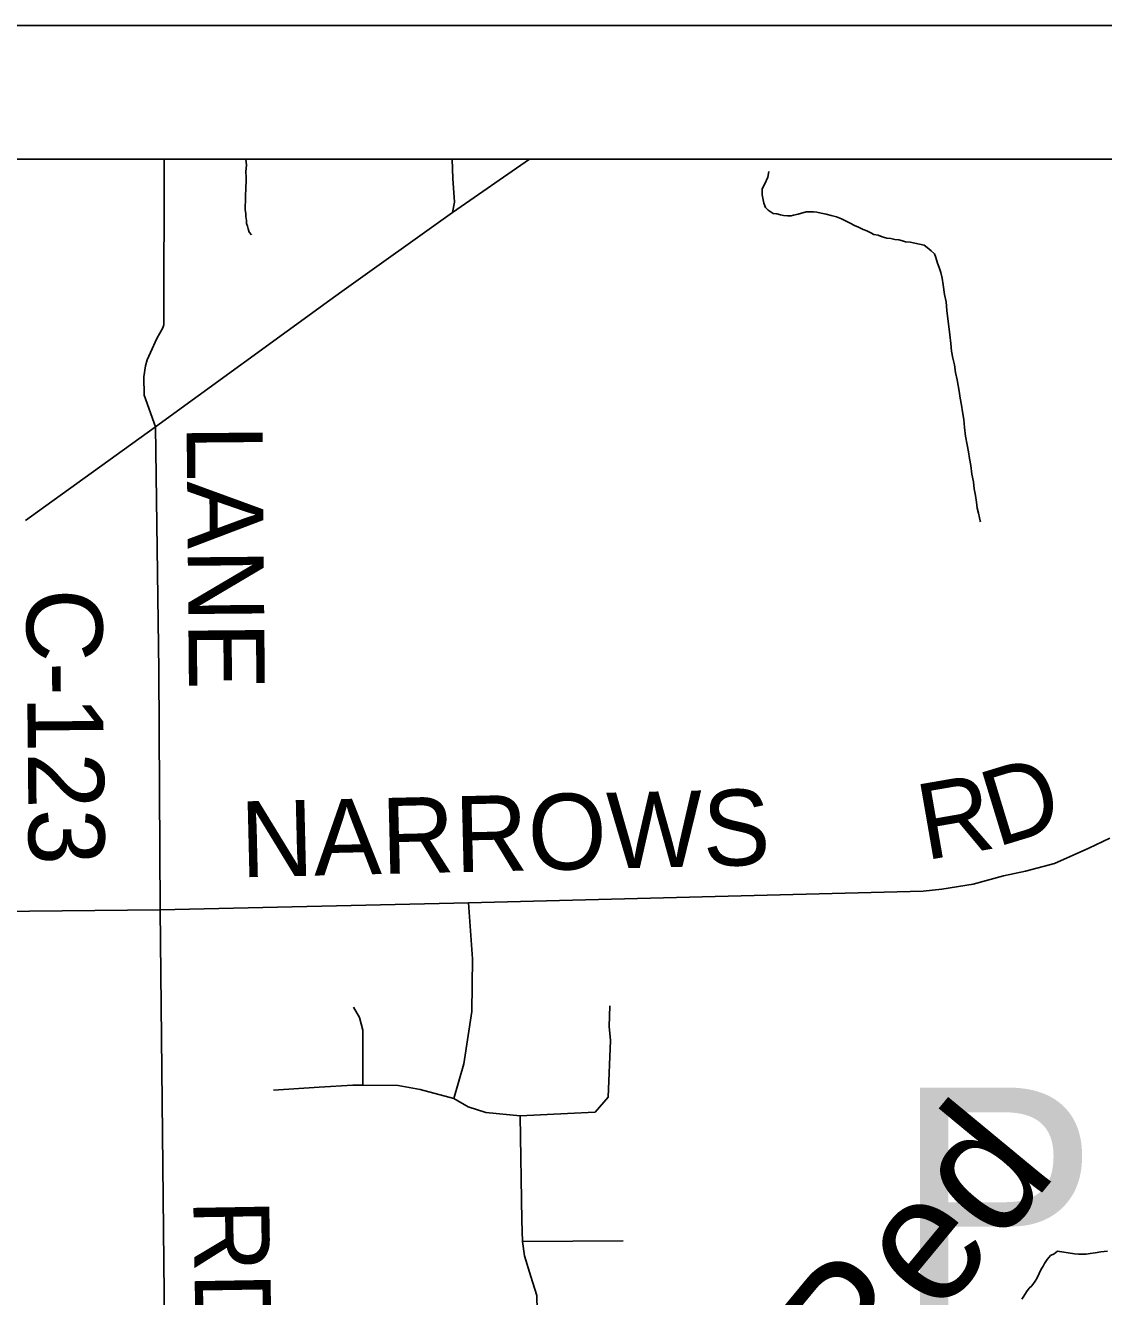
# Model space of a CAD drawing. Extents: x -59 to 82, y -3 to 49.
# Drawn here: x -50.187 to -49.38, y 48.44 to 49.391 of the extents above; entities that cross this region are included whole.
import ezdxf

# ---------------------------------------------------------------- set-up
doc = ezdxf.new("R2010")
doc.units = 0
for name, color, linetype in [('GM_X_Corporation', 7, 'Continuous'), ('GM_X_County_Road', 7, 'Continuous'), ('GM_X_County_Road_Text', 7, 'Continuous'), ('GM_X_Minor_River', 7, 'Continuous'), ('GM_X_Minor_River_Text', 7, 'Continuous'), ('GM_X_Township_Road', 7, 'Continuous'), ('GM_X_Township_Text', 7, 'Continuous'), ('GM_X_US_Route', 7, 'Continuous'), ('SH_Data', 7, 'Continuous')]:
    doc.layers.add(name, color=color, linetype=linetype)

msp = doc.modelspace()

# ---------------------------------------------------------------- linework, layer by layer
at = {"layer": 'GM_X_Corporation'}
for q in [(-52.22423, 49.29125), (-50.61637, 49.29125)]:
    msp.add_line((-48.09799, 49.29125), q, dxfattribs=at)
at = {"layer": 'GM_X_County_Road'}
for p, q in [((-49.86685, 49.27668), (-49.86733, 49.29125)), ((-49.86551, 49.25902), (-49.86685, 49.27668)), ((-49.86708, 49.2512), (-49.86551, 49.25902)), ((-50.08932, 49.09087), (-50.0869, 48.90877)), ((-50.0869, 48.90877), (-50.08577, 48.72919)), ((-49.39063, 48.77544), (-49.37487, 48.78285)), ((-49.41646, 48.76386), (-49.39063, 48.77544)), ((-49.43812, 48.75822), (-49.41646, 48.76386)), ((-49.4773, 48.74842), (-49.45445, 48.75466)), ((-49.45445, 48.75466), (-49.43812, 48.75822)), ((-49.85497, 48.7345), (-49.5147, 48.74338)), ((-49.5147, 48.74338), (-49.50075, 48.74486)), ((-49.50075, 48.74486), (-49.4773, 48.74842)), ((-50.08577, 48.72919), (-49.85497, 48.7345)), ((-50.26352, 48.72766), (-50.08577, 48.72919)), ((-50.08577, 48.72919), (-50.08012, 48.18116))]:
    msp.add_line(p, q, dxfattribs=at)
at = {"layer": 'GM_X_Minor_River'}
for p, q in [((-50.02174, 49.29125), (-50.02128, 49.2866)), ((-50.02128, 49.2866), (-50.02157, 49.28203)), ((-50.02157, 49.28203), (-50.02148, 49.27747)), ((-50.02148, 49.27747), (-50.02141, 49.27405)), ((-49.6309, 49.27773), (-49.63308, 49.27274)), ((-49.63022, 49.28193), (-49.6309, 49.27773)), ((-49.6309, 49.27773), (-49.63022, 49.28193)), ((-49.63022, 49.28193), (-49.6309, 49.27773)), ((-50.02166, 49.26796), (-50.02198, 49.26492)), ((-50.02198, 49.26492), (-50.02193, 49.26225)), ((-50.02141, 49.27405), (-50.02172, 49.27062)), ((-50.02172, 49.27062), (-50.02166, 49.26796)), ((-49.63308, 49.27274), (-49.63529, 49.2689)), ((-49.63529, 49.2689), (-49.6352, 49.26434)), ((-50.02188, 49.25959), (-50.02219, 49.25617)), ((-50.02219, 49.25617), (-50.02212, 49.25312)), ((-50.02193, 49.26225), (-50.02188, 49.25959)), ((-49.6352, 49.26434), (-49.63393, 49.25828)), ((-49.63393, 49.25828), (-49.63272, 49.25488)), ((-50.02212, 49.25312), (-50.02169, 49.25047)), ((-50.02169, 49.25047), (-50.02164, 49.24819)), ((-50.02164, 49.24819), (-50.0212, 49.24516)), ((-49.63272, 49.25488), (-49.63077, 49.25302)), ((-49.63077, 49.25302), (-49.62691, 49.25044)), ((-49.62691, 49.25044), (-49.62424, 49.25011)), ((-49.62424, 49.25011), (-49.62155, 49.2494)), ((-49.62155, 49.2494), (-49.61926, 49.24907)), ((-49.61926, 49.24907), (-49.61621, 49.24875)), ((-49.61621, 49.24875), (-49.61354, 49.24881)), ((-49.61354, 49.24881), (-49.61164, 49.24922)), ((-49.61164, 49.24922), (-49.60823, 49.25005)), ((-49.60823, 49.25005), (-49.60217, 49.2517)), ((-49.60217, 49.2517), (-49.60026, 49.25174)), ((-49.60026, 49.25174), (-49.59684, 49.25181)), ((-49.59684, 49.25181), (-49.59416, 49.25148)), ((-49.59416, 49.25148), (-49.5911, 49.25078)), ((-49.5911, 49.25078), (-49.58727, 49.2501)), ((-49.58727, 49.2501), (-49.58344, 49.24903)), ((-49.58344, 49.24903), (-49.57961, 49.24797)), ((-49.57961, 49.24797), (-49.57577, 49.24653)), ((-49.57577, 49.24653), (-49.5723, 49.2447)), ((-50.0212, 49.24516), (-50.02115, 49.24288)), ((-50.02115, 49.24288), (-50.02035, 49.24099)), ((-50.02035, 49.24099), (-50.01993, 49.2391)), ((-50.01993, 49.2391), (-50.01912, 49.23645)), ((-50.01912, 49.23645), (-50.01755, 49.23459)), ((-49.5723, 49.2447), (-49.56922, 49.24324)), ((-49.56922, 49.24324), (-49.56614, 49.2414)), ((-49.56614, 49.2414), (-49.56307, 49.24032)), ((-49.56307, 49.24032), (-49.5596, 49.23849)), ((-49.5596, 49.23849), (-49.55691, 49.23741)), ((-49.55691, 49.23741), (-49.55383, 49.23595)), ((-49.55383, 49.23595), (-49.55152, 49.23485)), ((-49.55152, 49.23485), (-49.54846, 49.23416)), ((-49.54846, 49.23416), (-49.54539, 49.23308)), ((-49.54539, 49.23308), (-49.54194, 49.23201)), ((-49.54194, 49.23201), (-49.53889, 49.23169)), ((-49.53889, 49.23169), (-49.53582, 49.23099)), ((-49.53582, 49.23099), (-49.53277, 49.23067)), ((-49.53277, 49.23067), (-49.53009, 49.22996)), ((-49.53009, 49.22996), (-49.52779, 49.22925)), ((-49.52779, 49.22925), (-49.52435, 49.22894)), ((-49.52435, 49.22894), (-49.5209, 49.22825)), ((-49.5209, 49.22825), (-49.51746, 49.22756)), ((-49.51746, 49.22756), (-49.51402, 49.22687)), ((-49.51402, 49.22687), (-49.51169, 49.22502)), ((-49.51169, 49.22502), (-49.50859, 49.22242)), ((-49.50859, 49.22242), (-49.50626, 49.22018)), ((-49.50626, 49.22018), (-49.50506, 49.21755)), ((-49.50506, 49.21755), (-49.50383, 49.21339)), ((-49.50383, 49.21339), (-49.50262, 49.20999)), ((-49.50262, 49.20999), (-49.5014, 49.20621)), ((-49.5014, 49.20621), (-49.50056, 49.20205)), ((-49.50056, 49.20205), (-49.49969, 49.19712)), ((-49.49969, 49.19712), (-49.49878, 49.18992)), ((-49.49878, 49.18992), (-49.49753, 49.18424)), ((-49.49753, 49.18424), (-49.49701, 49.17779)), ((-49.49701, 49.17779), (-49.49474, 49.15958)), ((-49.49474, 49.15958), (-49.49384, 49.15314)), ((-49.49384, 49.15314), (-49.49334, 49.14744)), ((-49.49334, 49.14744), (-49.49247, 49.14214)), ((-49.49247, 49.14214), (-49.49123, 49.13722)), ((-49.49123, 49.13722), (-49.49035, 49.13154)), ((-49.49035, 49.13154), (-49.48909, 49.12586)), ((-49.48909, 49.12586), (-49.48778, 49.11752)), ((-49.48778, 49.11752), (-49.48691, 49.11221)), ((-49.48691, 49.11221), (-49.48604, 49.10691)), ((-49.48604, 49.10691), (-49.48518, 49.10198)), ((-49.48518, 49.10198), (-49.4843, 49.0963)), ((-49.4843, 49.0963), (-49.48379, 49.09022)), ((-49.48379, 49.09022), (-49.4829, 49.08378)), ((-49.4829, 49.08378), (-49.48162, 49.07734)), ((-49.48162, 49.07734), (-49.48076, 49.07204)), ((-49.48076, 49.07204), (-49.47989, 49.06711)), ((-49.47989, 49.06711), (-49.47902, 49.06181)), ((-49.47902, 49.06181), (-49.47813, 49.05536)), ((-49.47813, 49.05536), (-49.47687, 49.04968)), ((-49.47687, 49.04968), (-49.47638, 49.04437)), ((-49.47638, 49.04437), (-49.47552, 49.03945)), ((-49.47552, 49.03945), (-49.47465, 49.03452)), ((-49.47465, 49.03452), (-49.47418, 49.02997)), ((-49.47418, 49.02997), (-49.47334, 49.02618)), ((-49.47334, 49.02618), (-49.47251, 49.02277)), ((-49.47251, 49.02277), (-49.47208, 49.0205)), ((-49.47208, 49.0205), (-49.47168, 49.01975)), ((-49.42377, 48.46448), (-49.42193, 48.46756)), ((-49.42193, 48.46756), (-49.41932, 48.47065)), ((-49.41932, 48.47065), (-49.41668, 48.47185)), ((-49.41668, 48.47185), (-49.41405, 48.47381)), ((-49.41405, 48.47381), (-49.40143, 48.47178)), ((-49.40143, 48.47178), (-49.39838, 48.47146)), ((-49.39838, 48.47146), (-49.39495, 48.47153)), ((-49.39495, 48.47153), (-49.39267, 48.47158)), ((-49.39267, 48.47158), (-49.38963, 48.47202)), ((-49.38963, 48.47202), (-49.38583, 48.47248)), ((-49.38583, 48.47248), (-49.38165, 48.47332)), ((-49.38165, 48.47332), (-49.37671, 48.4738)), ((-49.42964, 48.45334), (-49.42781, 48.45717)), ((-49.42781, 48.45717), (-49.42635, 48.46024)), ((-49.42635, 48.46024), (-49.42487, 48.46256)), ((-49.42487, 48.46256), (-49.42377, 48.46448)), ((-49.4352, 48.446), (-49.43334, 48.44794)), ((-49.43334, 48.44794), (-49.43074, 48.45141)), ((-49.43074, 48.45141), (-49.42964, 48.45334)), ((-49.44076, 48.4379), (-49.43928, 48.44021)), ((-49.43928, 48.44021), (-49.43743, 48.44329)), ((-49.43743, 48.44329), (-49.4352, 48.446))]:
    msp.add_line(p, q, dxfattribs=at)
at = {"layer": 'GM_X_Township_Road'}
for p, q in [((-50.08317, 49.16714), (-50.08279, 49.29125)), ((-50.08836, 49.15702), (-50.08382, 49.16502)), ((-50.08382, 49.16502), (-50.08317, 49.16714)), ((-50.09311, 49.1465), (-50.08836, 49.15702)), ((-50.09679, 49.13658), (-50.0956, 49.14094)), ((-50.0956, 49.14094), (-50.09311, 49.1465)), ((-50.09798, 49.12829), (-50.09679, 49.13658)), ((-50.09772, 49.11458), (-50.09798, 49.12829)), ((-50.08932, 49.09087), (-50.09772, 49.11458)), ((-49.85194, 48.69267), (-49.85497, 48.7345)), ((-49.8525, 48.65331), (-49.85194, 48.69267)), ((-49.93668, 48.64863), (-49.94108, 48.65634)), ((-49.7496, 48.64203), (-49.74933, 48.65744)), ((-49.93421, 48.63928), (-49.93668, 48.64863)), ((-49.85847, 48.61402), (-49.8525, 48.65331)), ((-49.93416, 48.59798), (-49.93421, 48.63928)), ((-49.74878, 48.63157), (-49.7496, 48.64203)), ((-49.75042, 48.58907), (-49.74878, 48.63157)), ((-49.86589, 48.58818), (-49.85847, 48.61402)), ((-50.00106, 48.59442), (-49.96682, 48.59649)), ((-49.96682, 48.59649), (-49.94159, 48.59798)), ((-49.94159, 48.59798), (-49.93416, 48.59798)), ((-49.93416, 48.59798), (-49.90775, 48.59769)), ((-49.90775, 48.59769), (-49.89112, 48.59472)), ((-49.89112, 48.59472), (-49.86589, 48.58818)), ((-49.86589, 48.58818), (-49.85521, 48.58195)), ((-49.85521, 48.58195), (-49.84215, 48.57749)), ((-49.76021, 48.57779), (-49.75042, 48.58907)), ((-49.84215, 48.57749), (-49.81632, 48.57512)), ((-49.81632, 48.57512), (-49.781, 48.5769)), ((-49.81513, 48.49673), (-49.81632, 48.57512)), ((-49.781, 48.5769), (-49.76021, 48.57779)), ((-49.81454, 48.48099), (-49.81513, 48.49673)), ((-49.81454, 48.48099), (-49.73914, 48.48158)), ((-49.81305, 48.4703), (-49.81454, 48.48099)), ((-49.80843, 48.45473), (-49.81305, 48.4703)), ((-49.80373, 48.44064), (-49.80843, 48.45473)), ((-49.80256, 48.3863), (-49.80373, 48.44064))]:
    msp.add_line(p, q, dxfattribs=at)
at = {"layer": 'GM_X_US_Route'}
for p, q in [((-49.86708, 49.2512), (-49.80941, 49.29125)), ((-49.94982, 49.19217), (-49.86708, 49.2512)), ((-49.95892, 49.18568), (-49.94982, 49.19217)), ((-50.08932, 49.09087), (-49.95892, 49.18568)), ((-50.17767, 49.02719), (-50.08932, 49.09087)), ((-50.18669, 49.02081), (-50.17767, 49.02719))]:
    msp.add_line(p, q, dxfattribs=at)
at = {"layer": 'SH_Data'}
for p, q in [((-54.99799, 49.39125), (-47.99799, 49.39125)), ((-54.89799, 49.29125), (-48.09799, 49.29125))]:
    msp.add_line(p, q, dxfattribs=at)

# ---------------------------------------------------------------- texts
at = {"layer": 'GM_X_County_Road_Text'}
for s, height, rotation, p in [('LANE', 0.056818, 270.51589, (-50.06603, 49.09226)), ('C-123', 0.056818, 270.55166, (-50.18606, 48.96945)), ('D', 0.05682, 16.96814, (-49.45976, 48.77603)), ('R', 0.05682, 9.84859, (-49.51311, 48.76629)), ('NARROWS', 0.056818, 1.37094, (-50.02522, 48.75358)), ('RD', 0.056818, 270.98725, (-50.06104, 48.51244))]:
    msp.add_text(s, height=height, rotation=rotation, dxfattribs=at).set_placement(p)
at = {"layer": 'GM_X_Minor_River_Text'}
msp.add_text('Red', height=0.094751, rotation=50.42054, dxfattribs=at).set_placement((-49.5617, 48.35308))
at = {"layer": 'GM_X_Township_Text'}
msp.add_text('PERRY', height=0.170455, rotation=0.00001, dxfattribs=at).set_placement((-49.53571, 48.42579))

doc.saveas('drawing.dxf')
